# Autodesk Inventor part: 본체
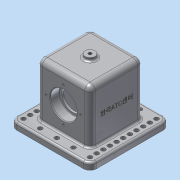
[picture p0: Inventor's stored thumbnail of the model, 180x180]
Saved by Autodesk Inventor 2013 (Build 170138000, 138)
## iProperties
Created: 2018-11
Part Number: 본체
Material: 알루미늄 6061
Document SubType Name: Modeling
Designer: Administrator
Density: 2.71 g/cm^3
Mass: 1020.76 g
Surface Area: 777.082 cm^2
Volume: 376.663 cm^3
Author: Administrator
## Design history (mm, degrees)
sketch "스케치1"
  geometry: 1 further point
sketch "스케치2"
  geometry: L1 (-60, 60)-(60, 60); L2 (60, 60)-(60, -60); L3 (60, -60)-(-60, -60); L4 (-60, -60)-(-60, 60); 3 further points
  constraints: 8 end point, 2 midpoint, 2 parallel, 1 horizontal, 1 horizontal alignment, 1 perpendicular, 1 vertical alignment
  dimensions: "d7" = 120 distance of L1.end L2.end; "d9" = 120 distance of L1.start L1.end
extrude "돌출1" new body sketch "스케치2" distance "d10" = 10; taper "d11" = 0 deg
fillet "모깎기1" dims "d12" = 10
sketch "스케치3"
  geometry: L1 (-40, 40)-(40, 40); L2 (40, 40)-(40, -40); L3 (40, -40)-(-40, -40); L4 (-40, -40)-(-40, 40); 3 further points
  constraints: 8 end point, 2 midpoint, 2 parallel, 1 horizontal, 1 horizontal alignment, 1 perpendicular, 1 vertical alignment
  dimensions: "d13" = 80 distance of L1.start L1.end; "d15" = 80 distance of L1.end L2.end
extrude "돌출2" join sketch "스케치3" distance "d16" = 80; taper "d17" = 0 deg
fillet "모깎기2" dims "d18" = 8
sketch "스케치4"
  geometry: L1 (30, -23)-(-30, -23); L2 (-30, -23)-(-30, 23); L3 (-30, 23)-(30, 23); L4 (30, 23)-(30, -23); 3 further points
  constraints: 8 end point, 2 midpoint, 2 parallel, 1 horizontal, 1 horizontal alignment, 1 perpendicular, 1 vertical alignment
  dimensions: "d19" = 60 distance of L1.start L1.end; "d21" = 46 distance of L1.end L2.end
extrude "돌출3" cut sketch "스케치4" distance "d22" = 80; taper "d23" = 0 deg
sketch "스케치5"
  geometry: C1 r 7.5 at (0, 0); 1 further point
  constraints: 1 centre point, 1 coincident
  dimensions: "d24" = 15 diameter of C1
extrude "돌출4" join sketch "스케치5" distance "d26" = 5; taper "d27" = 0 deg
fillet "모깎기3" dims "d28" = 8
sketch "스케치6"
  geometry: 1 further point
sketch "스케치7"
  geometry: L1 (40, 48)-(-40, 48); L2 (-40, 48)-(-40, 28); L3 (-40, 28)-(-26, 28); L4 (-26, 28)-(-26, 31.5); L5 (-26, 31.5)-(26, 31.5); L6 (26, 31.5)-(26, 28); L7 (26, 28)-(40, 28); L8 (40, 28)-(40, 48); L9 (40, 82)-(40, 10) reference; L10 (-40, 10)-(-40, 82) reference; L11 (23, 0)-(23, 80) reference; L12 (-23, 0)-(-23, 80) reference; L13 (-50, 0)-(50, 0) reference; 1 further point
  constraints: 16 end point, 6 parallel, 2 vertical alignment, 1 horizontal, 1 perpendicular
  dimensions: "d29" = 14 distance of L2.end L3.end; "d31" = 14 distance of L6.end L7.end; "d32" = 40 diameter of L7 L1; "d33" = 40 diameter of L3 L1; "d34" = 33 diameter of L5 L1; "d35" = 48 distance between parallel lines of L1 L13
revolve "회전1" sketch "스케치7" stored, may be unused: angle "d36" = 90 deg
chamfer "모따기1" distance "d37" = 1; stored, may be unused: second distance "d38" = 2, angle "d39" = 45 deg
fillet "모깎기4" dims "d40" = 0.6
sketch "스케치8"
  geometry: C1 r 21 at (32, 38) reference; 2 further points
  constraints: 1 vertical alignment
  dimensions: "d41" = 26 distance of point (32, 64) C1.centre
hole "구멍1" sketch "스케치8" at (32, 64) diameter "d42" = 3.242; stored, may be unused: countersink angle "d46" = 90 deg, drill point angle "d48" = 118 deg; dims "d43" = 8, "d44" = 4, "d45" = 2, "d47" = 10
hole "구멍2" diameter "d54" = 4.917; stored, may be unused: countersink angle "d58" = 90 deg, drill point angle "d60" = 118 deg; dims "d52" = 10, "d53" = 10, "d55" = 8, "d56" = 4, "d57" = 2, "d59" = 10
sketch "스케치9"
  geometry: A1 r 10 centre (-50, 50) between (-50, 60) and (-60, 50) reference; 1 further point
hole "구멍3" sketch "스케치9" at (-50, 50) diameter "d61" = 6.6; stored, may be unused: countersink angle "d65" = 90 deg, drill point angle "d67" = 118 deg; dims "d62" = 8, "d63" = 4, "d64" = 2, "d66" = 10
fillet "모깎기5" dims "d80" = 3
fillet "모깎기6" dims "d81" = 3
sketch "스케치10"
  geometry: L1 (0, 0)-(0, 64) reference; L2 (82, 82)-(82, -18) reference; 4 further points
  constraints: 2 horizontal alignment, 2 midpoint, 1 other
  dimensions: "d82" = 48 distance from line of L2 point (34, 32)
feature "엠보싱1" sketch "스케치10" dims "d7" = 120, "d9" = 120, "d83" = 0.5, "d84" = 0
node "솔리드1"
pattern_circular "원형 패턴1" dims angle "d50" = 360 deg
mirror "대칭1"
pattern_linear "직사각형 패턴3" dims "d76" = 10
mirror "대칭4"
pattern_linear "직사각형 패턴4" dims "d79" = 25
mirror "대칭5"
